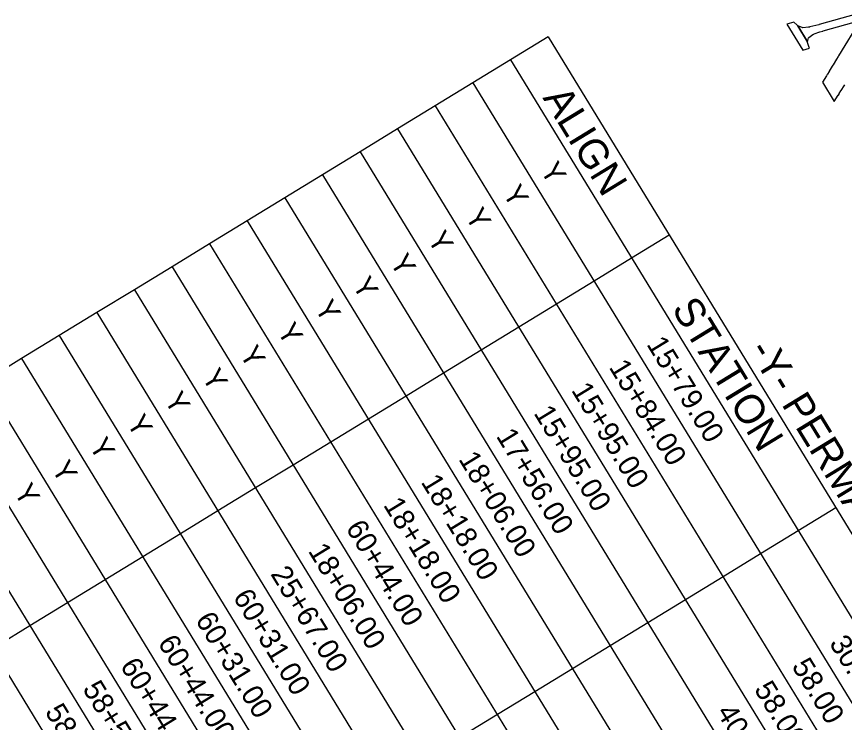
# Model space of a CAD drawing. Extents: x 1753086 to 1770987, y 792577 to 812636.
# Drawn here: x 1764623 to 1766380, y 803112 to 804610 of the extents above; entities that cross this region are included whole.
import ezdxf

# ---------------------------------------------------------------- set-up
doc = ezdxf.new("R2010")
doc.units = 0
for name, color, linetype in [('CTL Sheet Notes CELL', 7, 'Continuous'), ('CTL Sheet Table Cell', 7, 'Continuous'), ('CTL Sheet Text', 7, 'Continuous'), ('Sheet Data Field CELL', 7, 'Continuous')]:
    doc.layers.add(name, color=color, linetype=linetype)

msp = doc.modelspace()

# ---------------------------------------------------------------- linework, layer by layer
at = {"layer": 'CTL Sheet Table Cell'}
for p, q in [((1765751, 804567), (1765671.2, 804518.2)), ((1765751, 804567), (1767551.4, 801620.3)), ((1765671.2, 804518.2), (1765591.4, 804469.4)), ((1765671.2, 804518.2), (1767471.6, 801571.5)), ((1765591.4, 804469.4), (1765511.6, 804420.7)), ((1765591.4, 804469.4), (1767391.8, 801522.7)), ((1765511.6, 804420.7), (1765431.7, 804371.9)), ((1765511.6, 804420.7), (1767312, 801474)), ((1765431.7, 804371.9), (1765351.9, 804323.1)), ((1765431.7, 804371.9), (1767232.2, 801425.2)), ((1765351.9, 804323.1), (1765272.1, 804274.4)), ((1765351.9, 804323.1), (1767152.4, 801376.4)), ((1765272.1, 804274.4), (1765192.3, 804225.6)), ((1765272.1, 804274.4), (1767072.5, 801327.6)), ((1765192.3, 804225.6), (1765112.5, 804176.8)), ((1765192.3, 804225.6), (1766992.7, 801278.9)), ((1765112.5, 804176.8), (1765032.7, 804128.1)), ((1765112.5, 804176.8), (1766912.9, 801230.1)), ((1766008.2, 804146), (1765928.4, 804097.2)), ((1765032.7, 804128.1), (1764952.8, 804079.3)), ((1765032.7, 804128.1), (1766833.1, 801181.3)), ((1765928.4, 804097.2), (1765848.6, 804048.5)), ((1764952.8, 804079.3), (1764873, 804030.5)), ((1764952.8, 804079.3), (1766753.3, 801132.6)), ((1765848.6, 804048.5), (1765768.8, 803999.7)), ((1764873, 804030.5), (1764793.2, 803981.7)), ((1764873, 804030.5), (1766673.5, 801083.8)), ((1765768.8, 803999.7), (1765688.9, 803950.9)), ((1764793.2, 803981.7), (1764713.4, 803933)), ((1764793.2, 803981.7), (1766593.6, 801035)), ((1765688.9, 803950.9), (1765609.1, 803902.2)), ((1764713.4, 803933), (1764633.6, 803884.2)), ((1764713.4, 803933), (1766513.8, 800986.3)), ((1765609.1, 803902.2), (1765529.3, 803853.4)), ((1764633.6, 803884.2), (1764553.8, 803835.4)), ((1764633.6, 803884.2), (1766434, 800937.5)), ((1765529.3, 803853.4), (1765449.5, 803804.6)), ((1764553.8, 803835.4), (1766354.2, 800888.7)), ((1765449.5, 803804.6), (1765369.7, 803755.9)), ((1764473.9, 803786.7), (1766274.4, 800840)), ((1765369.7, 803755.9), (1765289.9, 803707.1)), ((1764394.1, 803737.9), (1766194.6, 800791.2)), ((1765289.9, 803707.1), (1765210, 803658.3)), ((1764314.3, 803689.1), (1766114.7, 800742.4)), ((1765210, 803658.3), (1765130.2, 803609.6)), ((1765130.2, 803609.6), (1765050.4, 803560.8)), ((1765050.4, 803560.8), (1764970.6, 803512)), ((1766361.9, 803567.2), (1766282.1, 803518.4)), ((1764970.6, 803512), (1764890.8, 803463.3)), ((1766282.1, 803518.4), (1766202.2, 803469.7)), ((1766202.2, 803469.7), (1766122.4, 803420.9)), ((1764890.8, 803463.3), (1764811, 803414.5)), ((1766122.4, 803420.9), (1766042.6, 803372.1)), ((1764811, 803414.5), (1764731.1, 803365.7)), ((1764731.1, 803365.7), (1764651.3, 803317)), ((1766042.6, 803372.1), (1765962.8, 803323.3)), ((1764651.3, 803317), (1764571.5, 803268.2)), ((1765962.8, 803323.3), (1765883, 803274.6)), ((1765883, 803274.6), (1765803.2, 803225.8)), ((1765803.2, 803225.8), (1765723.3, 803177)), ((1765723.3, 803177), (1765643.5, 803128.3)), ((1765643.5, 803128.3), (1765563.7, 803079.5))]:
    msp.add_line(p, q, dxfattribs=at)
at = {"layer": 'Sheet Data Field CELL'}
for points in [[(1766405.1, 804615.4), (1766326.8, 804593.3), (1766325.9, 804593), (1766319.7, 804591.5), (1766306.9, 804588.2), (1766306.2, 804588.1), (1766303.8, 804587.9), (1766291.5, 804586.6), (1766290.6, 804587), (1766281.3, 804590.5), (1766302, 804556.6), (1766303.9, 804565.3), (1766304.3, 804565.6), (1766313.2, 804572.5), (1766315.3, 804573.2), (1766315.9, 804573.5), (1766328, 804577.9), (1766334.1, 804579.6), (1766335.1, 804579.9), (1766413.5, 804601.7)], [(1766413.5, 804601.7), (1766367.6, 804526.6), (1766367, 804525.7), (1766363.4, 804519.8), (1766356.1, 804507.8), (1766355.7, 804507.2), (1766354.4, 804505), (1766347.9, 804494.4), (1766347.5, 804493.8), (1766343.9, 804487.9), (1766343.4, 804487.1), (1766342, 804484.8), (1766341.9, 804484.5), (1766333.5, 804470.9), (1766358.6, 804429.9), (1766367.1, 804443.3), (1766367.2, 804443.6), (1766368.6, 804445.8), (1766369.2, 804446.7), (1766372.8, 804452.4), (1766373.2, 804453), (1766379.8, 804463.4), (1766381.2, 804465.5)]]:
    msp.add_lwpolyline(points, dxfattribs=at)
msp.add_lwpolyline([(1766272.4, 804598.2), (1766258.1, 804594.4), (1766291.9, 804539), (1766306.2, 804543), (1766305.6, 804544.5), (1766301.7, 804555.4), (1766302, 804556.6), (1766281.3, 804590.5), (1766278.9, 804592.6), (1766272.7, 804598.3)], close=True, dxfattribs=at)

# ---------------------------------------------------------------- texts
at = {"layer": 'CTL Sheet Notes CELL'}
for s, height, p in [('ALIGN', 62.36, (1765738.7, 804437.7)), ('STATION', 62.36, (1766012.2, 803990)), ('-Y- PERMANENT UTILITY EASEMENTS', 62.357, (1766175.4, 803902.2))]:
    msp.add_text(s, height=height, rotation=301.4249, dxfattribs=at).set_placement(p)
at = {"layer": 'CTL Sheet Text'}
for s, height, p in [('Y', 44.5, (1765733.3, 804284.2)), ('Y', 44.5, (1765653.5, 804235.4)), ('Y', 44.5, (1765573.7, 804186.6)), ('Y', 44.5, (1765493.8, 804137.8)), ('Y', 44.5, (1765414, 804089.1)), ('Y', 44.5, (1765334.2, 804040.3)), ('Y', 44.5, (1765254.4, 803991.5)), ('Y', 44.5, (1765174.6, 803942.8)), ('15+79.00', 44.54, (1765959, 803914.8)), ('Y', 44.5, (1765094.8, 803894)), ('15+84.00', 44.54, (1765879.2, 803866)), ('Y', 44.5, (1765014.9, 803845.2)), ('15+95.00', 44.54, (1765799.3, 803817.2)), ('Y', 44.5, (1764935.1, 803796.5)), ('Y', 44.5, (1764855.3, 803747.7)), ('15+95.00', 44.54, (1765719.5, 803768.5)), ('17+56.00', 44.54, (1765639.7, 803719.7)), ('Y', 44.5, (1764775.5, 803698.9)), ('18+06.00', 44.54, (1765559.9, 803670.9)), ('Y', 44.5, (1764695.7, 803650.2)), ('18+18.00', 44.54, (1765480.1, 803622.2)), ('Y', 44.5, (1764615.9, 803601.4)), ('18+18.00', 44.54, (1765400.3, 803573.4)), ('60+44.00', 44.54, (1765320.4, 803524.6)), ('18+06.00', 44.54, (1765240.6, 803475.9)), ('25+67.00', 44.54, (1765160.8, 803427.1)), ('60+31.00', 44.54, (1765081, 803378.3)), ('60+31.00', 44.54, (1765001.2, 803329.6)), ('60+44.00', 44.54, (1764921.4, 803280.8)), ('30.00', 44.54, (1766346.8, 803280)), ('60+44.00', 44.54, (1764841.5, 803232)), ('58.00', 44.54, (1766267, 803231.3)), ('58+50.09', 44.54, (1764761.7, 803183.3)), ('58.00', 44.54, (1766187.2, 803182.5)), ('58+48.19', 44.54, (1764681.9, 803134.5)), ('40.00', 44.54, (1766107.4, 803133.7))]:
    msp.add_text(s, height=height, rotation=301.4249, dxfattribs=at).set_placement(p)

doc.saveas('drawing.dxf')
